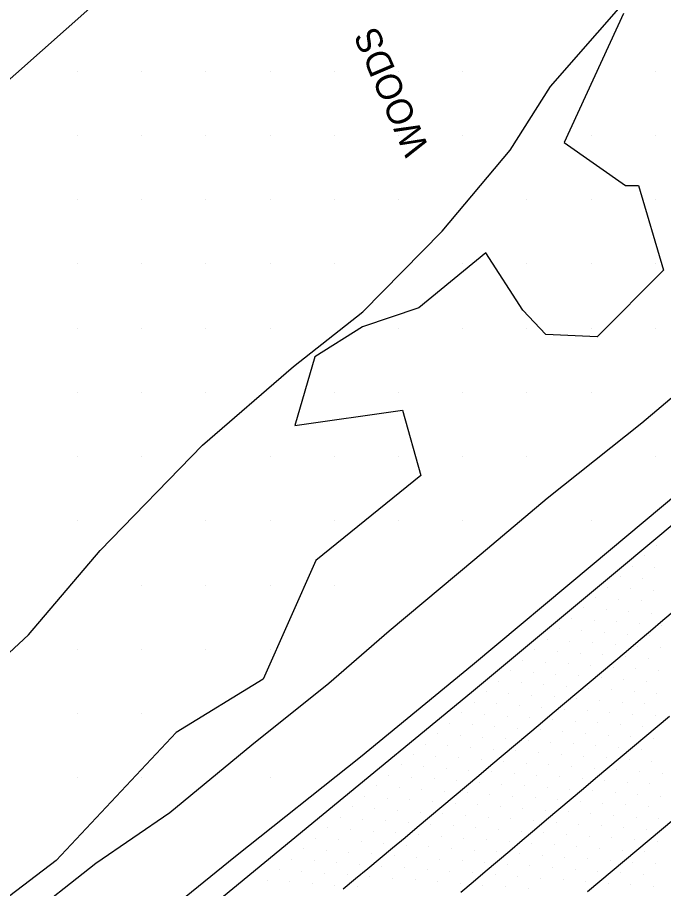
# Model space of a CAD drawing. Extents: x 1548934 to 1561348, y 809680 to 824075.
# Drawn here: x 1551460.6 to 1551561.3, y 810532.7 to 810668.3 of the extents above; entities that cross this region are included whole.
import ezdxf

# ---------------------------------------------------------------- set-up
doc = ezdxf.new("R2010")
doc.units = 0
for name, color, linetype in [('E_NCDOT_Vertical_Profile_Ground_Line', 7, 'Continuous'), ('Exist DTM QL2 LIDAR Elevation Point', 7, 'Continuous'), ('Exist DTM Scan Elevation Point', 7, 'Continuous'), ('Exist Vegetation Woods Line', 7, 'Continuous'), ('Exist Vegetation Woods Line Text', 7, 'Continuous'), ('P_RDY_Dimension_Text', 7, 'Continuous'), ('P_RDY_Terminator_Cell', 7, 'Continuous'), ('PH Exist DTM Breakline', 7, 'Continuous')]:
    doc.layers.add(name, color=color, linetype=linetype)

msp = doc.modelspace()

# ---------------------------------------------------------------- linework, layer by layer
at = {"layer": 'E_NCDOT_Vertical_Profile_Ground_Line'}
msp.add_lwpolyline([(1551391.75, 810450.16), (1551415.18, 810468.67), (1551438.59, 810487.39), (1551461.86, 810506.26), (1551485.06, 810525.28), (1551508.26, 810544.3), (1551531.35, 810563.29), (1551554.37, 810582.49), (1551577.41, 810601.69), (1551600.3, 810621.05), (1551623.11, 810640.53), (1551645.93, 810660)], dxfattribs=at)
at = {"layer": 'Exist DTM QL2 LIDAR Elevation Point'}
for p, q in [((1551469.98, 810659.98), (1551469.98, 810659.98)), ((1551479.98, 810659.98), (1551479.98, 810659.98)), ((1551489.98, 810659.98), (1551489.98, 810659.98)), ((1551499.98, 810659.98), (1551499.98, 810659.98)), ((1551509.98, 810659.98), (1551509.98, 810659.98)), ((1551519.98, 810659.98), (1551519.98, 810659.98)), ((1551529.98, 810659.98), (1551529.98, 810659.98)), ((1551559.98, 810659.98), (1551559.98, 810659.98)), ((1551469.98, 810649.98), (1551469.98, 810649.98)), ((1551479.98, 810649.98), (1551479.98, 810649.98)), ((1551489.98, 810649.98), (1551489.98, 810649.98)), ((1551499.98, 810649.98), (1551499.98, 810649.98)), ((1551509.98, 810649.98), (1551509.98, 810649.98)), ((1551519.98, 810649.98), (1551519.98, 810649.98)), ((1551529.98, 810649.98), (1551529.98, 810649.98)), ((1551549.98, 810649.98), (1551549.98, 810649.98)), ((1551559.98, 810649.98), (1551559.98, 810649.98)), ((1551469.98, 810639.98), (1551469.98, 810639.98)), ((1551479.98, 810639.98), (1551479.98, 810639.98)), ((1551489.98, 810639.98), (1551489.98, 810639.98)), ((1551499.98, 810639.98), (1551499.98, 810639.98)), ((1551509.98, 810639.98), (1551509.98, 810639.98)), ((1551519.98, 810639.98), (1551519.98, 810639.98)), ((1551539.98, 810639.98), (1551539.98, 810639.98)), ((1551549.98, 810639.98), (1551549.98, 810639.98)), ((1551559.98, 810639.98), (1551559.98, 810639.98)), ((1551469.98, 810629.98), (1551469.98, 810629.98)), ((1551479.98, 810629.98), (1551479.98, 810629.98)), ((1551489.98, 810629.98), (1551489.98, 810629.98)), ((1551499.98, 810629.98), (1551499.98, 810629.98)), ((1551509.98, 810629.98), (1551509.98, 810629.98)), ((1551529.98, 810629.98), (1551529.98, 810629.98)), ((1551539.98, 810629.98), (1551539.98, 810629.98)), ((1551549.98, 810629.98), (1551549.98, 810629.98)), ((1551559.98, 810629.98), (1551559.98, 810629.98)), ((1551469.98, 810619.98), (1551469.98, 810619.98)), ((1551479.98, 810619.98), (1551479.98, 810619.98)), ((1551489.98, 810619.98), (1551489.98, 810619.98)), ((1551499.98, 810619.98), (1551499.98, 810619.98)), ((1551519.98, 810619.98), (1551519.98, 810619.98)), ((1551529.98, 810619.98), (1551529.98, 810619.98)), ((1551539.98, 810619.98), (1551539.98, 810619.98)), ((1551549.98, 810619.98), (1551549.98, 810619.98)), ((1551559.98, 810619.98), (1551559.98, 810619.98)), ((1551469.98, 810609.98), (1551469.98, 810609.98)), ((1551479.98, 810609.98), (1551479.98, 810609.98)), ((1551489.98, 810609.98), (1551489.98, 810609.98)), ((1551509.98, 810609.98), (1551509.98, 810609.98)), ((1551519.98, 810609.98), (1551519.98, 810609.98)), ((1551529.98, 810609.98), (1551529.98, 810609.98)), ((1551539.98, 810609.98), (1551539.98, 810609.98)), ((1551549.98, 810609.98), (1551549.98, 810609.98)), ((1551469.98, 810599.98), (1551469.98, 810599.98)), ((1551479.98, 810599.98), (1551479.98, 810599.98)), ((1551499.98, 810599.98), (1551499.98, 810599.98)), ((1551509.98, 810599.98), (1551509.98, 810599.98)), ((1551519.98, 810599.98), (1551519.98, 810599.98)), ((1551529.98, 810599.98), (1551529.98, 810599.98)), ((1551539.98, 810599.98), (1551539.98, 810599.98)), ((1551559.98, 810599.98), (1551559.98, 810599.98)), ((1551469.98, 810589.98), (1551469.98, 810589.98)), ((1551489.98, 810589.98), (1551489.98, 810589.98)), ((1551499.98, 810589.98), (1551499.98, 810589.98)), ((1551509.98, 810589.98), (1551509.98, 810589.98)), ((1551519.98, 810589.98), (1551519.98, 810589.98)), ((1551529.98, 810589.98), (1551529.98, 810589.98)), ((1551549.98, 810589.98), (1551549.98, 810589.98)), ((1551479.98, 810579.98), (1551479.98, 810579.98)), ((1551489.98, 810579.98), (1551489.98, 810579.98)), ((1551499.98, 810579.98), (1551499.98, 810579.98)), ((1551509.98, 810579.98), (1551509.98, 810579.98)), ((1551469.98, 810569.98), (1551469.98, 810569.98)), ((1551479.98, 810569.98), (1551479.98, 810569.98)), ((1551489.98, 810569.98), (1551489.98, 810569.98)), ((1551499.98, 810569.98), (1551499.98, 810569.98)), ((1551469.98, 810559.98), (1551469.98, 810559.98)), ((1551479.98, 810559.98), (1551479.98, 810559.98)), ((1551489.98, 810559.98), (1551489.98, 810559.98)), ((1551469.98, 810549.97), (1551469.98, 810549.97)), ((1551479.98, 810549.97), (1551479.98, 810549.97)), ((1551499.98, 810549.97), (1551499.98, 810549.97))]:
    msp.add_line(p, q, dxfattribs=at)
at = {"layer": 'Exist DTM Scan Elevation Point'}
for p, q in [((1551560.19, 810586.19), (1551560.19, 810586.19)), ((1551558.29, 810584.56), (1551558.29, 810584.56)), ((1551556.4, 810582.93), (1551556.4, 810582.93)), ((1551559.92, 810582.66), (1551559.92, 810582.66)), ((1551554.5, 810581.3), (1551554.5, 810581.3)), ((1551558.03, 810581.04), (1551558.03, 810581.04)), ((1551552.6, 810579.67), (1551552.6, 810579.67)), ((1551556.13, 810579.41), (1551556.13, 810579.41)), ((1551559.65, 810579.14), (1551559.65, 810579.14)), ((1551550.71, 810578.05), (1551550.71, 810578.05)), ((1551554.23, 810577.78), (1551554.23, 810577.78)), ((1551557.76, 810577.51), (1551557.76, 810577.51)), ((1551548.81, 810576.42), (1551548.81, 810576.42)), ((1551552.34, 810576.15), (1551552.34, 810576.15)), ((1551555.86, 810575.88), (1551555.86, 810575.88)), ((1551546.91, 810574.79), (1551546.91, 810574.79)), ((1551550.44, 810574.52), (1551550.44, 810574.52)), ((1551559.39, 810575.61), (1551559.39, 810575.61)), ((1551545.02, 810573.16), (1551545.02, 810573.16)), ((1551553.96, 810574.25), (1551553.96, 810574.25)), ((1551557.49, 810573.98), (1551557.49, 810573.98)), ((1551561.01, 810573.72), (1551561.01, 810573.72)), ((1551548.54, 810572.89), (1551548.54, 810572.89)), ((1551552.07, 810572.62), (1551552.07, 810572.62)), ((1551555.59, 810572.36), (1551555.59, 810572.36)), ((1551559.12, 810572.09), (1551559.12, 810572.09)), ((1551543.12, 810571.53), (1551543.12, 810571.53)), ((1551546.65, 810571.26), (1551546.65, 810571.26)), ((1551550.17, 810570.99), (1551550.17, 810570.99)), ((1551553.7, 810570.73), (1551553.7, 810570.73)), ((1551557.22, 810570.46), (1551557.22, 810570.46)), ((1551541.23, 810569.9), (1551541.23, 810569.9)), ((1551544.75, 810569.63), (1551544.75, 810569.63)), ((1551548.28, 810569.37), (1551548.28, 810569.37)), ((1551551.8, 810569.1), (1551551.8, 810569.1)), ((1551560.75, 810570.19), (1551560.75, 810570.19)), ((1551539.33, 810568.27), (1551539.33, 810568.27)), ((1551542.85, 810568), (1551542.85, 810568)), ((1551546.38, 810567.74), (1551546.38, 810567.74)), ((1551555.33, 810568.83), (1551555.33, 810568.83)), ((1551558.85, 810568.56), (1551558.85, 810568.56)), ((1551537.43, 810566.64), (1551537.43, 810566.64)), ((1551540.96, 810566.38), (1551540.96, 810566.38)), ((1551549.9, 810567.47), (1551549.9, 810567.47)), ((1551553.43, 810567.2), (1551553.43, 810567.2)), ((1551556.95, 810566.93), (1551556.95, 810566.93)), ((1551560.48, 810566.67), (1551560.48, 810566.67)), ((1551535.54, 810565.01), (1551535.54, 810565.01)), ((1551544.48, 810566.11), (1551544.48, 810566.11)), ((1551548.01, 810565.84), (1551548.01, 810565.84)), ((1551551.53, 810565.57), (1551551.53, 810565.57)), ((1551555.06, 810565.3), (1551555.06, 810565.3)), ((1551558.58, 810565.04), (1551558.58, 810565.04)), ((1551539.06, 810564.75), (1551539.06, 810564.75)), ((1551542.59, 810564.48), (1551542.59, 810564.48)), ((1551546.11, 810564.21), (1551546.11, 810564.21)), ((1551549.64, 810563.94), (1551549.64, 810563.94)), ((1551553.16, 810563.68), (1551553.16, 810563.68)), ((1551533.64, 810563.39), (1551533.64, 810563.39)), ((1551537.16, 810563.12), (1551537.16, 810563.12)), ((1551540.69, 810562.85), (1551540.69, 810562.85)), ((1551544.21, 810562.58), (1551544.21, 810562.58)), ((1551547.74, 810562.31), (1551547.74, 810562.31)), ((1551556.69, 810563.41), (1551556.69, 810563.41)), ((1551560.21, 810563.14), (1551560.21, 810563.14)), ((1551531.74, 810561.76), (1551531.74, 810561.76)), ((1551535.27, 810561.49), (1551535.27, 810561.49)), ((1551538.79, 810561.22), (1551538.79, 810561.22)), ((1551542.32, 810560.95), (1551542.32, 810560.95)), ((1551551.26, 810562.05), (1551551.26, 810562.05)), ((1551554.79, 810561.78), (1551554.79, 810561.78)), ((1551558.32, 810561.51), (1551558.32, 810561.51)), ((1551529.85, 810560.13), (1551529.85, 810560.13)), ((1551533.37, 810559.86), (1551533.37, 810559.86)), ((1551536.9, 810559.59), (1551536.9, 810559.59)), ((1551545.84, 810560.69), (1551545.84, 810560.69)), ((1551549.37, 810560.42), (1551549.37, 810560.42)), ((1551552.89, 810560.15), (1551552.89, 810560.15)), ((1551556.42, 810559.88), (1551556.42, 810559.88)), ((1551559.94, 810559.61), (1551559.94, 810559.61)), ((1551527.95, 810558.5), (1551527.95, 810558.5)), ((1551531.48, 810558.23), (1551531.48, 810558.23)), ((1551540.42, 810559.32), (1551540.42, 810559.32)), ((1551543.95, 810559.06), (1551543.95, 810559.06)), ((1551547.47, 810558.79), (1551547.47, 810558.79)), ((1551551, 810558.52), (1551551, 810558.52)), ((1551554.52, 810558.25), (1551554.52, 810558.25)), ((1551526.05, 810556.87), (1551526.05, 810556.87)), ((1551535, 810557.96), (1551535, 810557.96)), ((1551538.53, 810557.7), (1551538.53, 810557.7)), ((1551542.05, 810557.43), (1551542.05, 810557.43)), ((1551545.58, 810557.16), (1551545.58, 810557.16)), ((1551549.1, 810556.89), (1551549.1, 810556.89)), ((1551558.05, 810557.99), (1551558.05, 810557.99)), ((1551529.58, 810556.6), (1551529.58, 810556.6)), ((1551533.1, 810556.33), (1551533.1, 810556.33)), ((1551536.63, 810556.07), (1551536.63, 810556.07)), ((1551540.15, 810555.8), (1551540.15, 810555.8)), ((1551543.68, 810555.53), (1551543.68, 810555.53)), ((1551552.63, 810556.62), (1551552.63, 810556.62)), ((1551556.15, 810556.36), (1551556.15, 810556.36)), ((1551559.68, 810556.09), (1551559.68, 810556.09)), ((1551524.16, 810555.24), (1551524.16, 810555.24)), ((1551527.68, 810554.97), (1551527.68, 810554.97)), ((1551531.21, 810554.71), (1551531.21, 810554.71)), ((1551534.73, 810554.44), (1551534.73, 810554.44)), ((1551538.26, 810554.17), (1551538.26, 810554.17)), ((1551547.2, 810555.26), (1551547.2, 810555.26)), ((1551550.73, 810555), (1551550.73, 810555)), ((1551554.25, 810554.73), (1551554.25, 810554.73)), ((1551557.78, 810554.46), (1551557.78, 810554.46)), ((1551522.26, 810553.61), (1551522.26, 810553.61)), ((1551525.79, 810553.34), (1551525.79, 810553.34)), ((1551529.31, 810553.08), (1551529.31, 810553.08)), ((1551532.84, 810552.81), (1551532.84, 810552.81)), ((1551541.78, 810553.9), (1551541.78, 810553.9)), ((1551545.31, 810553.63), (1551545.31, 810553.63)), ((1551548.83, 810553.37), (1551548.83, 810553.37)), ((1551552.36, 810553.1), (1551552.36, 810553.1)), ((1551555.88, 810552.83), (1551555.88, 810552.83)), ((1551520.37, 810551.98), (1551520.37, 810551.98)), ((1551523.89, 810551.72), (1551523.89, 810551.72)), ((1551527.42, 810551.45), (1551527.42, 810551.45)), ((1551536.36, 810552.54), (1551536.36, 810552.54)), ((1551539.89, 810552.27), (1551539.89, 810552.27)), ((1551543.41, 810552), (1551543.41, 810552)), ((1551546.94, 810551.74), (1551546.94, 810551.74)), ((1551550.46, 810551.47), (1551550.46, 810551.47)), ((1551559.41, 810552.56), (1551559.41, 810552.56)), ((1551518.47, 810550.35), (1551518.47, 810550.35)), ((1551521.99, 810550.09), (1551521.99, 810550.09)), ((1551530.94, 810551.18), (1551530.94, 810551.18)), ((1551534.47, 810550.91), (1551534.47, 810550.91)), ((1551537.99, 810550.64), (1551537.99, 810550.64)), ((1551541.52, 810550.38), (1551541.52, 810550.38)), ((1551545.04, 810550.11), (1551545.04, 810550.11)), ((1551553.99, 810551.2), (1551553.99, 810551.2)), ((1551557.51, 810550.93), (1551557.51, 810550.93)), ((1551561.04, 810550.67), (1551561.04, 810550.67)), ((1551516.57, 810548.73), (1551516.57, 810548.73)), ((1551525.52, 810549.82), (1551525.52, 810549.82)), ((1551529.04, 810549.55), (1551529.04, 810549.55)), ((1551532.57, 810549.28), (1551532.57, 810549.28)), ((1551536.09, 810549.01), (1551536.09, 810549.01)), ((1551539.62, 810548.75), (1551539.62, 810548.75)), ((1551548.57, 810549.84), (1551548.57, 810549.84)), ((1551552.09, 810549.57), (1551552.09, 810549.57)), ((1551555.62, 810549.31), (1551555.62, 810549.31)), ((1551559.14, 810549.04), (1551559.14, 810549.04)), ((1551520.1, 810548.46), (1551520.1, 810548.46)), ((1551523.62, 810548.19), (1551523.62, 810548.19)), ((1551527.15, 810547.92), (1551527.15, 810547.92)), ((1551530.67, 810547.65), (1551530.67, 810547.65)), ((1551534.2, 810547.39), (1551534.2, 810547.39)), ((1551543.14, 810548.48), (1551543.14, 810548.48)), ((1551546.67, 810548.21), (1551546.67, 810548.21)), ((1551550.19, 810547.94), (1551550.19, 810547.94)), ((1551553.72, 810547.68), (1551553.72, 810547.68)), ((1551557.24, 810547.41), (1551557.24, 810547.41)), ((1551514.68, 810547.1), (1551514.68, 810547.1)), ((1551518.2, 810546.83), (1551518.2, 810546.83)), ((1551521.73, 810546.56), (1551521.73, 810546.56)), ((1551525.25, 810546.29), (1551525.25, 810546.29)), ((1551528.78, 810546.02), (1551528.78, 810546.02)), ((1551537.72, 810547.12), (1551537.72, 810547.12)), ((1551541.25, 810546.85), (1551541.25, 810546.85)), ((1551544.77, 810546.58), (1551544.77, 810546.58)), ((1551548.3, 810546.32), (1551548.3, 810546.32)), ((1551551.82, 810546.05), (1551551.82, 810546.05)), ((1551560.77, 810547.14), (1551560.77, 810547.14)), ((1551512.78, 810545.47), (1551512.78, 810545.47)), ((1551516.3, 810545.2), (1551516.3, 810545.2)), ((1551519.83, 810544.93), (1551519.83, 810544.93)), ((1551523.35, 810544.66), (1551523.35, 810544.66)), ((1551532.3, 810545.76), (1551532.3, 810545.76)), ((1551535.83, 810545.49), (1551535.83, 810545.49)), ((1551539.35, 810545.22), (1551539.35, 810545.22)), ((1551542.88, 810544.95), (1551542.88, 810544.95)), ((1551546.4, 810544.69), (1551546.4, 810544.69)), ((1551555.35, 810545.78), (1551555.35, 810545.78)), ((1551558.87, 810545.51), (1551558.87, 810545.51)), ((1551510.88, 810543.84), (1551510.88, 810543.84)), ((1551514.41, 810543.57), (1551514.41, 810543.57)), ((1551517.93, 810543.3), (1551517.93, 810543.3)), ((1551526.88, 810544.4), (1551526.88, 810544.4)), ((1551530.4, 810544.13), (1551530.4, 810544.13)), ((1551533.93, 810543.86), (1551533.93, 810543.86)), ((1551537.45, 810543.59), (1551537.45, 810543.59)), ((1551540.98, 810543.32), (1551540.98, 810543.32)), ((1551549.93, 810544.42), (1551549.93, 810544.42)), ((1551553.45, 810544.15), (1551553.45, 810544.15)), ((1551556.98, 810543.88), (1551556.98, 810543.88)), ((1551560.5, 810543.62), (1551560.5, 810543.62)), ((1551508.99, 810542.21), (1551508.99, 810542.21)), ((1551512.51, 810541.94), (1551512.51, 810541.94)), ((1551521.46, 810543.03), (1551521.46, 810543.03)), ((1551524.98, 810542.77), (1551524.98, 810542.77)), ((1551528.51, 810542.5), (1551528.51, 810542.5)), ((1551532.03, 810542.23), (1551532.03, 810542.23)), ((1551535.56, 810541.96), (1551535.56, 810541.96)), ((1551544.51, 810543.06), (1551544.51, 810543.06)), ((1551548.03, 810542.79), (1551548.03, 810542.79)), ((1551551.56, 810542.52), (1551551.56, 810542.52)), ((1551555.08, 810542.25), (1551555.08, 810542.25)), ((1551558.61, 810541.99), (1551558.61, 810541.99)), ((1551507.09, 810540.58), (1551507.09, 810540.58)), ((1551516.04, 810541.67), (1551516.04, 810541.67)), ((1551519.56, 810541.41), (1551519.56, 810541.41)), ((1551523.09, 810541.14), (1551523.09, 810541.14)), ((1551526.61, 810540.87), (1551526.61, 810540.87)), ((1551530.14, 810540.6), (1551530.14, 810540.6)), ((1551539.08, 810541.7), (1551539.08, 810541.7)), ((1551542.61, 810541.43), (1551542.61, 810541.43)), ((1551546.13, 810541.16), (1551546.13, 810541.16)), ((1551549.66, 810540.89), (1551549.66, 810540.89)), ((1551553.18, 810540.63), (1551553.18, 810540.63)), ((1551510.62, 810540.31), (1551510.62, 810540.31)), ((1551514.14, 810540.04), (1551514.14, 810540.04)), ((1551517.67, 810539.78), (1551517.67, 810539.78)), ((1551521.19, 810539.51), (1551521.19, 810539.51)), ((1551524.72, 810539.24), (1551524.72, 810539.24)), ((1551533.66, 810540.33), (1551533.66, 810540.33)), ((1551537.19, 810540.07), (1551537.19, 810540.07)), ((1551540.71, 810539.8), (1551540.71, 810539.8)), ((1551544.24, 810539.53), (1551544.24, 810539.53)), ((1551547.76, 810539.26), (1551547.76, 810539.26)), ((1551556.71, 810540.36), (1551556.71, 810540.36)), ((1551560.24, 810540.09), (1551560.24, 810540.09)), ((1551505.19, 810538.95), (1551505.19, 810538.95)), ((1551508.72, 810538.68), (1551508.72, 810538.68)), ((1551512.24, 810538.42), (1551512.24, 810538.42)), ((1551515.77, 810538.15), (1551515.77, 810538.15)), ((1551519.29, 810537.88), (1551519.29, 810537.88)), ((1551528.24, 810538.97), (1551528.24, 810538.97)), ((1551531.77, 810538.71), (1551531.77, 810538.71)), ((1551535.29, 810538.44), (1551535.29, 810538.44)), ((1551538.82, 810538.17), (1551538.82, 810538.17)), ((1551542.34, 810537.9), (1551542.34, 810537.9)), ((1551551.29, 810539), (1551551.29, 810539)), ((1551554.81, 810538.73), (1551554.81, 810538.73)), ((1551558.34, 810538.46), (1551558.34, 810538.46)), ((1551503.3, 810537.32), (1551503.3, 810537.32)), ((1551506.82, 810537.05), (1551506.82, 810537.05)), ((1551510.35, 810536.79), (1551510.35, 810536.79)), ((1551513.87, 810536.52), (1551513.87, 810536.52)), ((1551522.82, 810537.61), (1551522.82, 810537.61)), ((1551526.34, 810537.34), (1551526.34, 810537.34)), ((1551529.87, 810537.08), (1551529.87, 810537.08)), ((1551533.39, 810536.81), (1551533.39, 810536.81)), ((1551536.92, 810536.54), (1551536.92, 810536.54)), ((1551545.87, 810537.63), (1551545.87, 810537.63)), ((1551549.39, 810537.37), (1551549.39, 810537.37)), ((1551552.92, 810537.1), (1551552.92, 810537.1)), ((1551556.44, 810536.83), (1551556.44, 810536.83)), ((1551559.97, 810536.57), (1551559.97, 810536.57)), ((1551501.4, 810535.69), (1551501.4, 810535.69)), ((1551504.93, 810535.43), (1551504.93, 810535.43)), ((1551508.45, 810535.16), (1551508.45, 810535.16)), ((1551517.4, 810536.25), (1551517.4, 810536.25)), ((1551520.92, 810535.98), (1551520.92, 810535.98)), ((1551524.45, 810535.72), (1551524.45, 810535.72)), ((1551527.97, 810535.45), (1551527.97, 810535.45)), ((1551531.5, 810535.18), (1551531.5, 810535.18)), ((1551540.44, 810536.27), (1551540.44, 810536.27)), ((1551543.97, 810536.01), (1551543.97, 810536.01)), ((1551547.49, 810535.74), (1551547.49, 810535.74)), ((1551551.02, 810535.47), (1551551.02, 810535.47)), ((1551554.55, 810535.2), (1551554.55, 810535.2)), ((1551499.5, 810534.06), (1551499.5, 810534.06)), ((1551503.03, 810533.8), (1551503.03, 810533.8)), ((1551511.98, 810534.89), (1551511.98, 810534.89)), ((1551515.5, 810534.62), (1551515.5, 810534.62)), ((1551519.03, 810534.35), (1551519.03, 810534.35)), ((1551522.55, 810534.09), (1551522.55, 810534.09)), ((1551526.08, 810533.82), (1551526.08, 810533.82)), ((1551535.02, 810534.91), (1551535.02, 810534.91)), ((1551538.55, 810534.64), (1551538.55, 810534.64)), ((1551542.07, 810534.38), (1551542.07, 810534.38)), ((1551545.6, 810534.11), (1551545.6, 810534.11)), ((1551549.12, 810533.84), (1551549.12, 810533.84)), ((1551558.07, 810534.94), (1551558.07, 810534.94)), ((1551506.55, 810533.53), (1551506.55, 810533.53)), ((1551510.08, 810533.26), (1551510.08, 810533.26)), ((1551513.6, 810532.99), (1551513.6, 810532.99)), ((1551529.6, 810533.55), (1551529.6, 810533.55)), ((1551533.13, 810533.28), (1551533.13, 810533.28)), ((1551536.65, 810533.02), (1551536.65, 810533.02)), ((1551540.18, 810532.75), (1551540.18, 810532.75)), ((1551552.65, 810533.57), (1551552.65, 810533.57)), ((1551556.18, 810533.31), (1551556.18, 810533.31)), ((1551559.7, 810533.04), (1551559.7, 810533.04))]:
    msp.add_line(p, q, dxfattribs=at)
at = {"layer": 'Exist Vegetation Woods Line'}
msp.add_lwpolyline([(1551555.04, 810668.94), (1551545.76, 810648.88), (1551555.32, 810642.16), (1551557.37, 810642.19), (1551561.24, 810628.98), (1551550.89, 810618.62), (1551542.92, 810618.99), (1551539.36, 810622.78), (1551533.57, 810631.67), (1551523.13, 810623.15), (1551514.34, 810620.19), (1551506.95, 810615.49), (1551503.82, 810604.83), (1551520.61, 810607.23), (1551523.46, 810597.03), (1551507.08, 810583.83), (1551498.88, 810565.32), (1551485.34, 810557.06), (1551466.66, 810537.13), (1551444.77, 810520.45)], dxfattribs=at)
at = {"layer": 'P_RDY_Dimension_Text'}
msp.add_lwpolyline([(1551558.11, 810746.33), (1551456.62, 810656.3), (1551333.17, 810546.96), (1551186.58, 810416.65)], dxfattribs=at)
at = {"layer": 'P_RDY_Terminator_Cell'}
for points in [[(1551511.35, 810532.71), (1551513.28, 810534.3), (1551515.21, 810535.89), (1551517.14, 810537.48), (1551519.06, 810539.08), (1551520.99, 810540.67), (1551522.9, 810542.28), (1551524.81, 810543.89), (1551526.72, 810545.5), (1551528.64, 810547.11), (1551530.55, 810548.73), (1551532.46, 810550.34), (1551534.37, 810551.95), (1551536.28, 810553.56), (1551538.2, 810555.17), (1551540.11, 810556.78), (1551542.02, 810558.39), (1551543.93, 810560), (1551545.85, 810561.61), (1551547.76, 810563.22), (1551549.67, 810564.83), (1551551.58, 810566.44), (1551553.49, 810568.05), (1551555.41, 810569.66), (1551557.32, 810571.27), (1551559.23, 810572.88), (1551561.14, 810574.5), (1551563.05, 810576.11)], [(1551562.16, 810559.54), (1551560.24, 810557.93), (1551558.33, 810556.33), (1551556.41, 810554.72), (1551554.5, 810553.11), (1551552.59, 810551.5), (1551550.68, 810549.89), (1551548.77, 810548.27), (1551546.86, 810546.66), (1551544.95, 810545.05), (1551543.04, 810543.43), (1551541.13, 810541.82), (1551539.22, 810540.21), (1551537.31, 810538.59), (1551535.4, 810536.98), (1551533.49, 810535.37), (1551531.58, 810533.75), (1551529.67, 810532.14)], [(1551562.83, 810543.48), (1551560.91, 810541.87), (1551559, 810540.27), (1551557.08, 810538.67), (1551555.16, 810537.06), (1551553.24, 810535.46), (1551551.32, 810533.86), (1551549.4, 810532.25)]]:
    msp.add_lwpolyline(points, dxfattribs=at)
at = {"layer": 'PH Exist DTM Breakline'}
for points in [[(1551372.12, 810479.59), (1551389.99, 810495.3), (1551400.65, 810506.84), (1551411.53, 810518.15), (1551427.33, 810537.4), (1551448.81, 810559.67), (1551462.35, 810572.24), (1551473.5, 810585.36), (1551489.47, 810601.74), (1551503.6, 810613.99), (1551514.42, 810622.53), (1551526.76, 810635.05), (1551537.34, 810647.7), (1551543.65, 810657.61), (1551558.31, 810674.34), (1551572.56, 810687.89), (1551583.53, 810698.87), (1551593.75, 810708.19), (1551612.18, 810728.73)], [(1551618.4, 810654.5), (1551608.52, 810647.49), (1551595.55, 810636.81), (1551578.09, 810621.8), (1551564.56, 810610.83), (1551557.87, 810605.16), (1551543.14, 810593.45), (1551531.85, 810583.95), (1551518.52, 810572.8), (1551509.1, 810564.66), (1551497.12, 810555.07), (1551484.36, 810544.52), (1551472.82, 810536.63), (1551461.26, 810527.53)], [(1551623.76, 810648.55), (1551611.65, 810637.66), (1551598.62, 810624.31), (1551581.6, 810609.45), (1551566.32, 810596.61), (1551550.14, 810583.07), (1551531.52, 810567.5), (1551514.04, 810553.21), (1551494.6, 810537.72), (1551475.14, 810521.96), (1551457.52, 810507.59), (1551444.99, 810497.86), (1551424.72, 810481.84), (1551402.56, 810464.19), (1551385.38, 810450.04)]]:
    msp.add_lwpolyline(points, dxfattribs=at)

# ---------------------------------------------------------------- texts
at = {"layer": 'Exist Vegetation Woods Line Text'}
msp.add_text('WOODS', height=4.02, rotation=113.1736, dxfattribs=at).set_placement((1551524.82, 810647.91))

doc.saveas('drawing.dxf')
